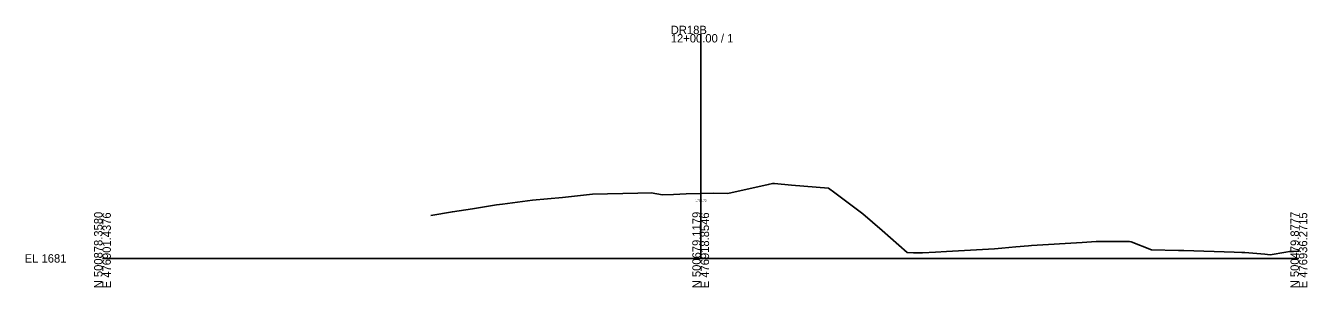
# Model space of a CAD drawing. Extents: x -26 to 403, y -10 to 2578.
# Drawn here: x -25.7 to 402.8, y 2490.3 to 2577.9 of the extents above; entities that cross this region are included whole.
import ezdxf

# ---------------------------------------------------------------- set-up
doc = ezdxf.new("R2010")
doc.units = 0
for name, color, linetype in [('Exist Cross Section Cell', 7, 'Continuous'), ('Exist XS Center Line Elevation Label', 7, 'Continuous'), ('Exist XS Ground Line', 7, 'Continuous')]:
    doc.layers.add(name, color=color, linetype=linetype)

msp = doc.modelspace()

# ---------------------------------------------------------------- linework, layer by layer
at = {"layer": 'Exist Cross Section Cell'}
for p, q in [((200, 2500), (200, 2575.05)), ((0, 2500), (200, 2500)), ((200, 2500), (400, 2500))]:
    msp.add_line(p, q, dxfattribs=at)
at = {"layer": 'Exist XS Ground Line'}
msp.add_lwpolyline([(109.75, 2514.37), (116.98, 2515.63), (123.71, 2516.58), (131.72, 2517.88), (133.75, 2518.15), (135.44, 2518.39), (143.79, 2519.52), (153.83, 2520.37), (154.86, 2520.48), (163.87, 2521.47), (179.01, 2521.81), (183.41, 2521.92), (187.29, 2521.23), (190.88, 2521.39), (195.1, 2521.56), (200, 2521.72), (204.39, 2521.87), (209.05, 2521.73), (222.62, 2524.71), (224, 2525.02), (224.69, 2525.01), (230.36, 2524.49), (242.71, 2523.51), (244.83, 2521.97), (254.23, 2514.95), (260.67, 2509.39), (269.01, 2502), (271.11, 2501.83), (274.17, 2501.84), (278.47, 2502.04), (282.18, 2502.27), (298.28, 2503.23), (300.64, 2503.43), (305.37, 2503.84), (309.65, 2504.19), (310.62, 2504.28), (327.53, 2505.37), (332.24, 2505.65), (341.2, 2505.68), (343.33, 2505.67), (343.96, 2505.52), (350.76, 2502.82), (359.75, 2502.65), (361.54, 2502.62), (378.37, 2502.06), (380.93, 2501.99), (381.94, 2501.93), (388.67, 2501.37), (390.41, 2501.22), (395.62, 2502.08), (396.86, 2502.27), (397.45, 2502.3), (398.23, 2502.33), (399.48, 2502.39), (400, 2502.42)], dxfattribs=at)

# ---------------------------------------------------------------- texts
at = {"layer": 'Exist Cross Section Cell'}
for s, p in [('DR18B', (190, 2575.05)), ('12+00.00 / 1', (190, 2572.25)), ('EL 1681', (-26, 2498.6))]:
    msp.add_text(s, height=2.8, dxfattribs=at).set_placement(p)
for s, p in [('N 500878.3580', (0, 2490)), ('E 476901.4376', (2.8, 2490)), ('N 500679.1179', (200, 2490)), ('E 476918.8546', (202.8, 2490)), ('N 500479.8777', (400, 2490)), ('E 476936.2715', (402.8, 2490))]:
    msp.add_text(s, height=2.8, rotation=90, dxfattribs=at).set_placement(p)
at = {"layer": 'Exist XS Center Line Elevation Label'}
msp.add_text('1702.72', height=0.75, dxfattribs=at).set_placement((198.25, 2518.97))

doc.saveas('drawing.dxf')
